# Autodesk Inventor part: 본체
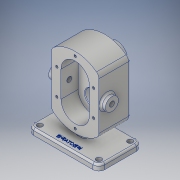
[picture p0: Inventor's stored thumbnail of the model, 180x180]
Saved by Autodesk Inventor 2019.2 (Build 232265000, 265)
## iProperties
Created: 2019-03
Part Number: 본체
Material: 알루미늄 6061
Document SubType Name: Modeling
Designer: User
Mass: 1187.16 g
Surface Area: 719.273 cm^2
Volume: 439.69 cm^3
Density: 2.7 g/cm^3
Appearance: 알루미늄 - 평지
Author: User
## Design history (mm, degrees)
sketch "스케치1"
  geometry: L1 (60, 73)-(-60, 73); L2 (-60, 73)-(-60, 0); L3 (-60, 0)-(60, 0); L4 (60, 0)-(60, 73); L5 (60, 73)-(-60, 0); L6 (-60, 73)-(60, 0); L7 (84, 0)-(-84, 0) reference; L8 (0, -14.6)-(0, 87.6) reference; 2 further points
  constraints: 12 end point, 3 midpoint, 2 parallel, 1 collinear, 1 horizontal, 1 perpendicular
  dimensions: "d0" = 73 distance between parallel lines of L3 L1; "d1" = 120 distance between parallel lines of L2 L4
extrude "돌출1" new body sketch "스케치1" distance "d2" = 10; taper "d3" = 0 deg
sketch "스케치2"
  geometry: L1 (0, -2)-(0, 12) reference; L2 (-40, 122.721)-(-40, 33.279); L3 (40, 122.721)-(40, 33.279); L4 (-40, 78)-(40, 78); L5 (-60, 0)-(60, 0) reference; L6 (-43.067, 138)-(65.49, 138); A1 r 60 centre (0, 78) between (40, 122.721) and (-40, 122.721); A2 r 60 centre (0, 78) between (-40, 33.279) and (40, 33.279); 1 further point
  constraints: 8 end point, 4 point on circle, 2 centre point, 2 midpoint, 2 point on line, 2 vertical, 1 horizontal, 1 tangent, 1 other
  dimensions: "d4" = 60 radius of A1; "d5" = 60 radius of A2; "d6" = 80 distance between parallel lines of L3 L2; "d7" = 78 distance between parallel lines of L5 L4; "d8" = 138 distance between parallel lines of L5 L6
extrude "돌출2" join sketch "스케치2" distance "d9" = 53; taper "d10" = 0 deg
sketch "스케치3"
  geometry: L1 (30, 43)-(0, 43); L2 (0, 43)-(0, 0); L3 (0, 0)-(30, 0); L4 (30, 0)-(30, 43); L5 (0, 0)-(10, 0) reference; L6 (0, 0)-(0, 73) reference
  constraints: 8 end point, 2 collinear, 2 parallel, 1 horizontal, 1 perpendicular
  dimensions: "d11" = 43 distance between parallel lines of L3 L1; "d12" = 30 distance between parallel lines of L6 L4
extrude "돌출3" join sketch "스케치3" stored distance "d13" = 12; taper "d14" = 0 deg
sketch "스케치4"
  geometry: L1 (-73, -33.279)-(0, -33.279) reference; L2 (-53, 0)-(-53, 89.443) reference; C1 r 11 at (-39, 44.721)
  constraints: 1 centre point
  dimensions: "d15" = 22 diameter of C1; "d16" = 78 distance from line of L1 C1.centre; "d17" = 14 distance from line of L2 C1.centre
extrude "돌출4" join sketch "스케치4" distance "d18" = 8; taper "d19" = 0 deg
fillet "모깎기1" dims "d20" = 3
sketch "스케치5"
  geometry: L1 (0, 56)-(0, 100); L2 (24, 56)-(24, 100); L3 (-24, 100)-(-24, 56); L4 (-60, 0)-(60, 0) reference; L5 (0, -27.6)-(0, 165.6) reference; A1 r 24 centre (0, 56) between (-24, 56) and (24, 56); A2 r 24 centre (0, 100) between (24, 100) and (-24, 100); 2 further points
  constraints: 8 end point, 4 point on circle, 4 tangent, 2 centre point, 1 collinear, 1 midpoint, 1 parallel, 1 vertical
  dimensions: "d21" = 24 radius of A2; "d22" = 44 distance of L1.start L1.end; "d23" = 78 distance from line of L4 point (0, 78)
extrude "돌출5" cut sketch "스케치5" distance "d24" = 29; taper "d25" = 0 deg
sketch "스케치6"
  geometry: C1 r 11 at (0, 0) reference; 2 further points
  constraints: 1 coincident
hole "구멍1" sketch "스케치6" at (0, 0) diameter "d26" = 8.376; stored, may be unused: countersink angle "d30" = 90 deg, drill point angle "d32" = 0 deg; dims "d27" = 20, "d28" = 4, "d29" = 2, "d31" = 8
fillet "모깎기2" dims "d33" = 3
sketch "스케치7"
  geometry: C1 r 11 at (0, 0) reference; 2 further points
  constraints: 1 coincident
hole "구멍2" sketch "스케치7" at (0, 0) diameter "d34" = 8.376; stored, may be unused: countersink angle "d38" = 90 deg, drill point angle "d40" = 0 deg; dims "d35" = 20, "d36" = 4, "d37" = 2, "d39" = 8
sketch "스케치8"
  geometry: C1 r 19 at (60, 100); A1 r 24 centre (60, 100) between (84, 100) and (36, 100) reference; 1 further point
  constraints: 1 centre point, 1 concentric
  dimensions: "d41" = 38 diameter of C1
extrude "돌출6" join sketch "스케치8" distance "d42" = 17; taper "d43" = 0 deg
sketch "스케치9"
  geometry: C1 r 14 at (0, 0); C2 r 19 at (0, 0) reference; 1 further point
  constraints: 1 centre point, 1 concentric
  dimensions: "d44" = 28 diameter of C1
extrude "돌출7" cut sketch "스케치9" distance "d45" = 7.3; taper "d46" = 0 deg
chamfer "모따기1" distance "d47" = 0.7; stored, may be unused: second distance "d48" = 2, angle "d49" = 30 deg
fillet "모깎기3" dims "d50" = 0.5
sketch "스케치10"
  geometry: A1 r 24 centre (0, 100) between (24, 100) and (-24, 100) reference; 2 further points
  constraints: 1 coincident
hole "구멍3" sketch "스케치10" at (0, 100) diameter "d51" = 17; stored, may be unused: countersink angle "d55" = 90 deg, drill point angle "d57" = 0 deg; dims "d52" = 20, "d53" = 25, "d54" = 15, "d56" = 27.3
sketch "스케치11"
  geometry: A1 r 24 centre (0, 56) between (-24, 56) and (24, 56) reference; 2 further points
  constraints: 1 coincident
hole "구멍4" sketch "스케치11" at (0, 56) diameter "d58" = 25; stored, may be unused: countersink angle "d62" = 90 deg, drill point angle "d64" = 0 deg; dims "d59" = 20, "d60" = 25, "d61" = 15, "d63" = 15
sketch "스케치12"
  geometry: L1 (24, 100)-(24, 56) reference; L2 (-24, 56)-(-24, 100) reference; L3 (31, 100)-(31, 56); L4 (-31, 56)-(-31, 100); A1 r 24 centre (0, 100) between (24, 100) and (-24, 100) reference; A2 r 24 centre (0, 56) between (-24, 56) and (24, 56) reference; A3 r 31 centre (0, 100) between (31, 100) and (-31, 100); A4 r 31 centre (0, 56) between (-31, 56) and (31, 56); 7 further points
  constraints: 6 point on circle, 4 coincident, 4 end point, 2 centre point, 3 other
  dimensions: "d66" = 31 radius of A3
hole "구멍5" sketch "스케치12" at (0, 131), (-31, 100), (31, 100), (31, 56), (-31, 56), (0, 25) diameter "d67" = 4.134; stored, may be unused: countersink angle "d71" = 90 deg, drill point angle "d73" = 118 deg; dims "d68" = 10, "d69" = 25, "d70" = 15, "d72" = 12
fillet "모깎기4" dims "d74" = 10
fillet "모깎기5" dims "d75" = 10
fillet "모깎기6" dims "d76" = 3
fillet "모깎기7" dims "d77" = 3
fillet "모깎기8" dims "d78" = 3
fillet "모깎기9" dims "d79" = 3
chamfer "모따기2" distance "d80" = 1; stored, may be unused: second distance "d81" = 2, angle "d82" = 45 deg
sketch "스케치13"
  geometry: A1 r 10 centre (-50, -63) between (-60, -63) and (-50, -73) reference; A2 r 10 centre (-50, -10) between (-50, 0) and (-60, -10) reference; A3 r 10 centre (50, -63) between (50, -73) and (60, -63) reference; A4 r 10 centre (50, -10) between (60, -10) and (50, 0) reference; 5 further points
  constraints: 4 coincident
hole "구멍6" sketch "스케치13" at (-50, -63), (-50, -10), (50, -63), (50, -10) diameter "d83" = 9; stored, may be unused: countersink angle "d87" = 90 deg, drill point angle "d89" = 118 deg; dims "d84" = 10, "d85" = 25, "d86" = 15, "d88" = 12
sketch "스케치14"
  geometry: L1 (-50, -73)-(50, -73) reference; L2 (-60, -10)-(-60, -63) reference; 2 further points
  constraints: 1 other
  dimensions: "d90" = 10 distance from line of L1 point (0, -63); "d91" = 60 distance from line of L2 point (0, -63)
feature "엠보싱1" sketch "스케치14" dims "d0" = 73, "d1" = 120, "d10" = 0, "d92" = 0.5, "d93" = 0
node "솔리드1"
mirror "미러1"
